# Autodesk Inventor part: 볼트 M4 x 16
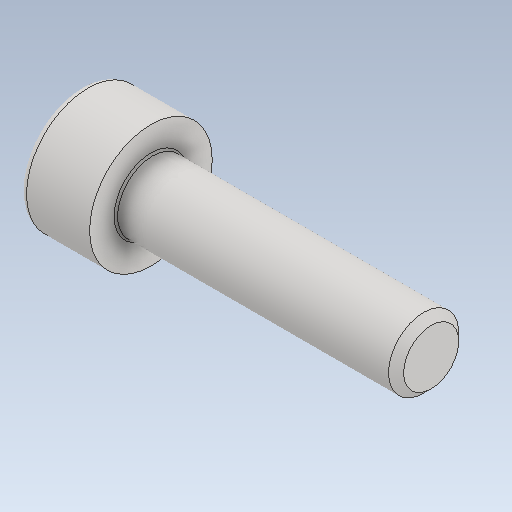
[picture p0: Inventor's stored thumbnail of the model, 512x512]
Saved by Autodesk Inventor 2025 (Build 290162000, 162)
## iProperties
Created: 2024-07
Part Number: 볼트 M4 x 16
Material: 스테인리스강
Description: 6각 소켓 머리 캡 나사
Document SubType Name: Modeling
Designer: 미서니
Density: 8.08 g/cm^3
Appearance: 기본값
Author: jhkim
Sending System: Autodesk Inventor 2025
Preprocessor: ST-DEVELOPER v20
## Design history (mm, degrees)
feature "Solid1"
node "솔리드1"
